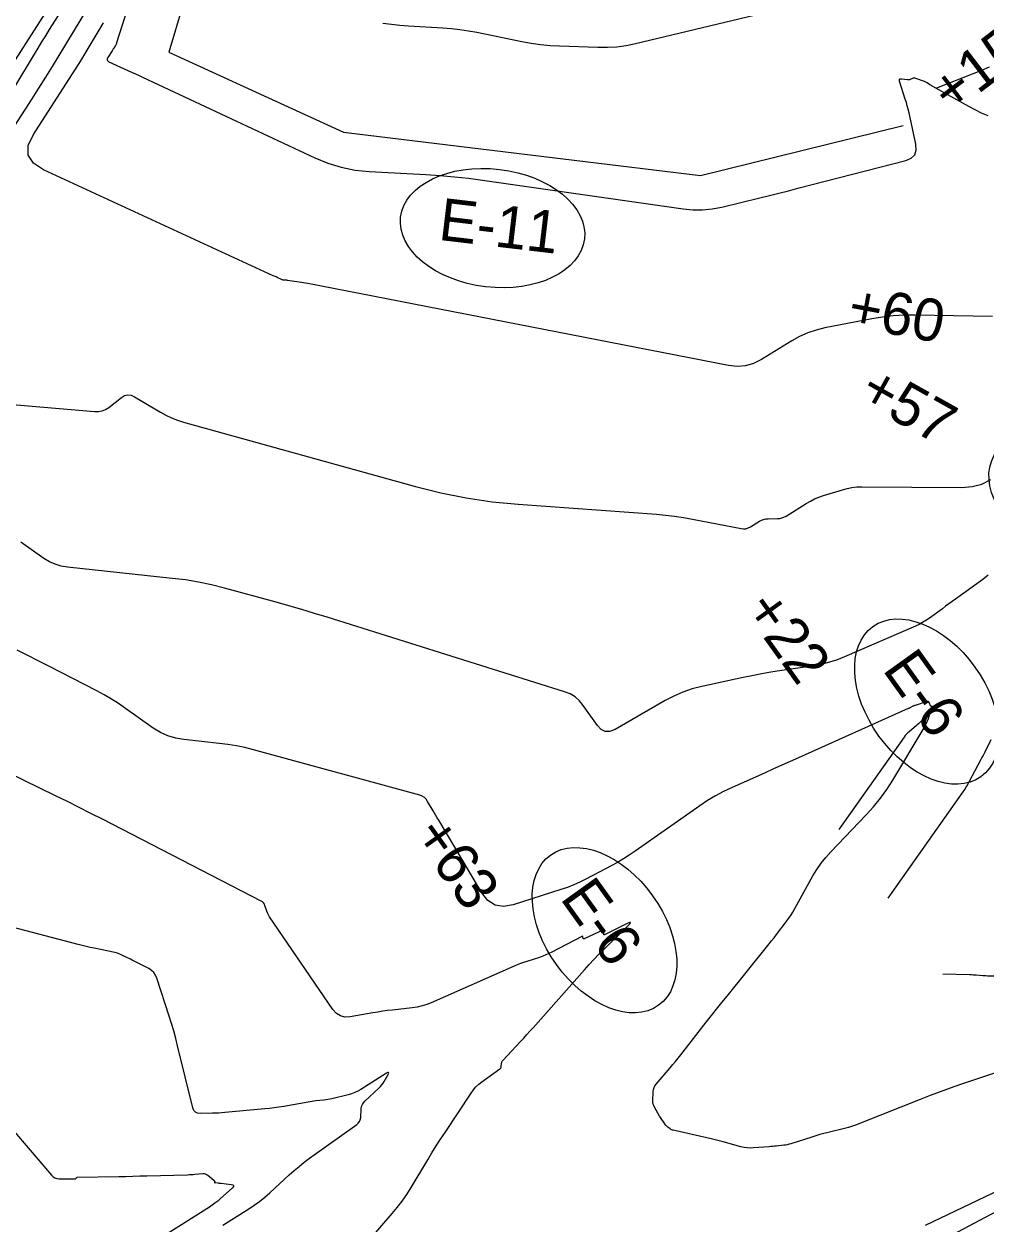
# Model space of a CAD drawing. Extents: x 1005228 to 1008882, y 1883389 to 1885754.
# Drawn here: x 1007862.3 to 1008004.6, y 1884352.9 to 1884530.4 of the extents above; entities that cross this region are included whole.
import ezdxf

# ---------------------------------------------------------------- set-up
doc = ezdxf.new("R2010")
doc.units = 0
for name, color, linetype in [('ATDIMS', 7, 'Continuous'), ('C-ANNO-NOTE', 7, 'Continuous'), ('R_Erosion', 7, 'Continuous'), ('S_BASELINE', 7, 'Continuous'), ('S_BRIDGE', 7, 'Continuous'), ('TSOBSTACLE', 7, 'Continuous')]:
    doc.layers.add(name, color=color, linetype=linetype)

msp = doc.modelspace()

# ---------------------------------------------------------------- linework, layer by layer
at = {"layer": 'ATDIMS'}
msp.add_lwpolyline([(1008005.05, 1884524.04), (1008003.94, 1884523.59), (1007997.3, 1884520.93)], dxfattribs=at)
at = {"layer": 'C-ANNO-NOTE'}
for points in [[(1007859.43, 1884522.69), (1007868.54, 1884536.99)], [(1007860.9, 1884521.17), (1007863.8, 1884525.98), (1007864.35, 1884526.89), (1007864.91, 1884527.8), (1007865.47, 1884528.71), (1007866.05, 1884529.61), (1007871.53, 1884538.23)], [(1007872.64, 1884534.47), (1007867.42, 1884525.79), (1007866.44, 1884524.17), (1007865.44, 1884522.56), (1007864.43, 1884520.96), (1007863.41, 1884519.36), (1007854.75, 1884505.98)], [(1007970.3, 1884531.71), (1007952.76, 1884527.51), (1007951.38, 1884527.23), (1007949.99, 1884527.04), (1007948.59, 1884526.95), (1007947.18, 1884526.96), (1007941.52, 1884527.16), (1007940.1, 1884527.24), (1007938.7, 1884527.37), (1007937.3, 1884527.57), (1007935.91, 1884527.82), (1007929.27, 1884529.17), (1007928.02, 1884529.4), (1007926.76, 1884529.58), (1007925.5, 1884529.73), (1007924.24, 1884529.83), (1007919.16, 1884530.14), (1007917.89, 1884530.23), (1007916.63, 1884530.36), (1007915.37, 1884530.52)], [(1008005.55, 1884487.18), (1007994.11, 1884487.37), (1007992.49, 1884487.36), (1007990.88, 1884487.26), (1007989.28, 1884487.08), (1007987.69, 1884486.81), (1007980.75, 1884485.46), (1007979.47, 1884485.16), (1007978.23, 1884484.74), (1007977.03, 1884484.21), (1007975.88, 1884483.57), (1007971.37, 1884480.78), (1007970.22, 1884480.2), (1007969.02, 1884479.86), (1007967.78, 1884479.76), (1007966.5, 1884479.9), (1007904.24, 1884492.05), (1007903.93, 1884492.11), (1007903.62, 1884492.16), (1007903.3, 1884492.21), (1007902.99, 1884492.26), (1007901.26, 1884492.51), (1007901.19, 1884492.52), (1007901.11, 1884492.53), (1007901.04, 1884492.53), (1007900.96, 1884492.54), (1007900.66, 1884492.55), (1007900.59, 1884492.56), (1007900.51, 1884492.58), (1007900.44, 1884492.6), (1007900.37, 1884492.63), (1007899.7, 1884492.94), (1007899.56, 1884493.01), (1007899.43, 1884493.07), (1007899.29, 1884493.13), (1007899.15, 1884493.19), (1007865.17, 1884508.86), (1007863.66, 1884509.84), (1007862.9, 1884511.04), (1007862.9, 1884512.46), (1007863.65, 1884514.1), (1007869.36, 1884522.92), (1007869.9, 1884523.77), (1007870.43, 1884524.61), (1007870.96, 1884525.47), (1007871.48, 1884526.33), (1007873.55, 1884529.77), (1007874.04, 1884530.64)], [(1007850.74, 1884474.99), (1007872.7, 1884473.08), (1007873.27, 1884473.08), (1007873.81, 1884473.19), (1007874.32, 1884473.4), (1007874.81, 1884473.71), (1007876.67, 1884475.17), (1007877.14, 1884475.45), (1007877.62, 1884475.56), (1007878.11, 1884475.51), (1007878.61, 1884475.29), (1007882.44, 1884473), (1007883.26, 1884472.54), (1007884.1, 1884472.14), (1007884.97, 1884471.81), (1007885.86, 1884471.53), (1007920.19, 1884462.01), (1007923.93, 1884461.07), (1007927.71, 1884460.32), (1007931.52, 1884459.75), (1007935.37, 1884459.38), (1007955.84, 1884457.89), (1007957.18, 1884457.77), (1007958.52, 1884457.61), (1007959.85, 1884457.41), (1007961.17, 1884457.18), (1007968.36, 1884455.77), (1007968.72, 1884455.73), (1007969.08, 1884455.76), (1007969.42, 1884455.86), (1007969.74, 1884456.03), (1007971.08, 1884456.85), (1007971.38, 1884457.01), (1007971.7, 1884457.13), (1007972.02, 1884457.2), (1007972.36, 1884457.23), (1007973.74, 1884457.25), (1007974.08, 1884457.28), (1007974.4, 1884457.36), (1007974.71, 1884457.47), (1007975.01, 1884457.63), (1007978.01, 1884459.5), (1007978.62, 1884459.85), (1007979.24, 1884460.16), (1007979.89, 1884460.43), (1007980.55, 1884460.66), (1007983.37, 1884461.53), (1007984.06, 1884461.72), (1007984.77, 1884461.85), (1007985.48, 1884461.93), (1007986.21, 1884461.95), (1008001.05, 1884461.85), (1008002.57, 1884461.98), (1008003.99, 1884462.37), (1008005.3, 1884463.04)], [(1008004.93, 1884448.87), (1008004.11, 1884448.25), (1008000.09, 1884445.33), (1007999.6, 1884444.97), (1007999.12, 1884444.62), (1007998.63, 1884444.27), (1007998.15, 1884443.92), (1007996.22, 1884442.52), (1007995.72, 1884442.18), (1007995.22, 1884441.87), (1007994.69, 1884441.59), (1007994.15, 1884441.34), (1007983.66, 1884436.79), (1007982.48, 1884436.32), (1007981.27, 1884435.93), (1007980.04, 1884435.62), (1007978.78, 1884435.4), (1007973.72, 1884434.65), (1007972.45, 1884434.45), (1007971.19, 1884434.23), (1007969.94, 1884433.99), (1007968.68, 1884433.73), (1007962.55, 1884432.4), (1007961.13, 1884432.04), (1007959.75, 1884431.57), (1007958.41, 1884430.99), (1007957.12, 1884430.31), (1007949.71, 1884426.04), (1007948.96, 1884425.73), (1007948.27, 1884425.73), (1007947.65, 1884426.02), (1007947.1, 1884426.62), (1007945.02, 1884429.6), (1007944.46, 1884430.29), (1007943.81, 1884430.85), (1007943.07, 1884431.3), (1007942.25, 1884431.63), (1007907.14, 1884442.64), (1007905.25, 1884443.22), (1007903.36, 1884443.79), (1007901.46, 1884444.34), (1007899.56, 1884444.87), (1007891.93, 1884446.95), (1007890.02, 1884447.44), (1007888.09, 1884447.84), (1007886.14, 1884448.17), (1007884.19, 1884448.41), (1007868.69, 1884450.06), (1007867.76, 1884450.22), (1007866.87, 1884450.49), (1007866.03, 1884450.87), (1007865.22, 1884451.37), (1007861.82, 1884453.78)], [(1008008.83, 1884376.17), (1008000.81, 1884373.49), (1007999.31, 1884372.97), (1007997.82, 1884372.44), (1007996.33, 1884371.88), (1007994.86, 1884371.3), (1007986.04, 1884367.77), (1007985.46, 1884367.55), (1007984.87, 1884367.34), (1007984.27, 1884367.16), (1007983.66, 1884367), (1007981.23, 1884366.41), (1007980.62, 1884366.26), (1007980.02, 1884366.09), (1007979.42, 1884365.92), (1007978.82, 1884365.73), (1007975.72, 1884364.73), (1007975.46, 1884364.65), (1007975.2, 1884364.59), (1007974.94, 1884364.54), (1007974.67, 1884364.51), (1007973.59, 1884364.39), (1007973.32, 1884364.36), (1007973.05, 1884364.34), (1007972.78, 1884364.31), (1007972.51, 1884364.29), (1007970.21, 1884364.11), (1007969.74, 1884364.09), (1007969.27, 1884364.12), (1007968.81, 1884364.18), (1007968.34, 1884364.29), (1007965.7, 1884365.02), (1007965.11, 1884365.18), (1007964.51, 1884365.33), (1007963.92, 1884365.48), (1007963.32, 1884365.61), (1007958.31, 1884366.72), (1007958.2, 1884366.76), (1007958.09, 1884366.8), (1007957.99, 1884366.85), (1007957.89, 1884366.92), (1007957.51, 1884367.21), (1007957.42, 1884367.28), (1007957.33, 1884367.37), (1007957.25, 1884367.45), (1007957.18, 1884367.55), (1007956.32, 1884368.77), (1007956.32, 1884368.77), (1007956.32, 1884368.78), (1007956.32, 1884368.78), (1007956.32, 1884368.78), (1007956.31, 1884368.8), (1007956.31, 1884368.8), (1007956.31, 1884368.8), (1007956.31, 1884368.81), (1007956.31, 1884368.81), (1007955.55, 1884370.14), (1007955.44, 1884370.37), (1007955.36, 1884370.61), (1007955.32, 1884370.85), (1007955.31, 1884371.1), (1007955.37, 1884372.46), (1007955.41, 1884372.76), (1007955.49, 1884373.05), (1007955.62, 1884373.31), (1007955.8, 1884373.56), (1007957.85, 1884375.96), (1007958.25, 1884376.44), (1007958.65, 1884376.92), (1007959.05, 1884377.41), (1007959.44, 1884377.91), (1007963.21, 1884382.74), (1007963.97, 1884383.7), (1007964.74, 1884384.67), (1007965.51, 1884385.63), (1007966.28, 1884386.59), (1007972.14, 1884393.85), (1007972.51, 1884394.31), (1007972.88, 1884394.77), (1007973.24, 1884395.23), (1007973.6, 1884395.7), (1007975.02, 1884397.57), (1007975.37, 1884398.05), (1007975.7, 1884398.53), (1007976.01, 1884399.03), (1007976.31, 1884399.54), (1007979, 1884404.37), (1007979.57, 1884405.33), (1007980.2, 1884406.24), (1007980.88, 1884407.11), (1007981.63, 1884407.94), (1007986.88, 1884413.41), (1007987.97, 1884414.61), (1007988.98, 1884415.86), (1007989.92, 1884417.17), (1007990.8, 1884418.53), (1007995.45, 1884426.28), (1007995.62, 1884426.58), (1007995.77, 1884426.89), (1007995.91, 1884427.2), (1007996.02, 1884427.53), (1007996.64, 1884429.45), (1007996.64, 1884429.47), (1007996.64, 1884429.48), (1007996.62, 1884429.49), (1007996.61, 1884429.48), (1007996.51, 1884429.43), (1007996.49, 1884429.42), (1007996.47, 1884429.42), (1007996.45, 1884429.43), (1007996.44, 1884429.45), (1007996.18, 1884430.03), (1007996.12, 1884430.11), (1007996.05, 1884430.17), (1007995.96, 1884430.18), (1007995.86, 1884430.17), (1007994.11, 1884429.61), (1007994.02, 1884429.58), (1007993.93, 1884429.54), (1007993.85, 1884429.51), (1007993.76, 1884429.47), (1007993.43, 1884429.3), (1007993.35, 1884429.25), (1007993.26, 1884429.21), (1007993.18, 1884429.17), (1007993.09, 1884429.13), (1007976.86, 1884421.86), (1007975.62, 1884421.3), (1007974.38, 1884420.75), (1007973.15, 1884420.2), (1007971.91, 1884419.64), (1007966.97, 1884417.43), (1007965.75, 1884416.85), (1007964.56, 1884416.21), (1007963.4, 1884415.51), (1007962.28, 1884414.76), (1007952.67, 1884408.02), (1007951.82, 1884407.44), (1007950.95, 1884406.89), (1007950.06, 1884406.36), (1007949.16, 1884405.87), (1007945.5, 1884403.94), (1007944.58, 1884403.48), (1007943.64, 1884403.06), (1007942.68, 1884402.68), (1007941.71, 1884402.35), (1007934.63, 1884400.1), (1007933.22, 1884399.85), (1007931.97, 1884400.06), (1007930.9, 1884400.73), (1007930.01, 1884401.86), (1007923.63, 1884412.62), (1007923.42, 1884412.96), (1007923.21, 1884413.31), (1007923.01, 1884413.66), (1007922.81, 1884414), (1007921.99, 1884415.4), (1007921.77, 1884415.72), (1007921.5, 1884415.97), (1007921.18, 1884416.17), (1007920.81, 1884416.31), (1007896.21, 1884423.04), (1007894.96, 1884423.36), (1007893.7, 1884423.62), (1007892.43, 1884423.83), (1007891.15, 1884423.99), (1007885.93, 1884424.55), (1007884.71, 1884424.75), (1007883.55, 1884425.11), (1007882.44, 1884425.61), (1007881.39, 1884426.26), (1007877.3, 1884429.16), (1007876.27, 1884429.87), (1007875.21, 1884430.54), (1007874.13, 1884431.17), (1007873.03, 1884431.76), (1007865.94, 1884435.42), (1007864.38, 1884436.21), (1007862.82, 1884437), (1007861.26, 1884437.78)], [(1007891.7, 1884352.67), (1007895.53, 1884355.08), (1007896.34, 1884355.62), (1007897.13, 1884356.19), (1007897.89, 1884356.81), (1007898.62, 1884357.45), (1007901.5, 1884360.11), (1007902.23, 1884360.76), (1007902.97, 1884361.39), (1007903.74, 1884361.99), (1007904.53, 1884362.58), (1007911.5, 1884367.56), (1007911.73, 1884367.77), (1007911.91, 1884368.01), (1007912.02, 1884368.29), (1007912.08, 1884368.6), (1007912.17, 1884369.91), (1007912.22, 1884370.23), (1007912.33, 1884370.52), (1007912.49, 1884370.78), (1007912.7, 1884371.02), (1007914.82, 1884373.01), (1007915.02, 1884373.22), (1007915.21, 1884373.45), (1007915.39, 1884373.68), (1007915.54, 1884373.93), (1007916.13, 1884374.96), (1007916.23, 1884375.17), (1007916.22, 1884375.27), (1007916.12, 1884375.27), (1007915.92, 1884375.16), (1007912.1, 1884372.77), (1007911.66, 1884372.51), (1007911.2, 1884372.3), (1007910.72, 1884372.12), (1007910.23, 1884371.98), (1007907.79, 1884371.4), (1007907.5, 1884371.33), (1007907.21, 1884371.28), (1007906.92, 1884371.23), (1007906.63, 1884371.19), (1007905.46, 1884371.06), (1007905.17, 1884371.03), (1007904.88, 1884370.99), (1007904.59, 1884370.94), (1007904.3, 1884370.9), (1007900.69, 1884370.27), (1007899.99, 1884370.15), (1007899.29, 1884370.05), (1007898.59, 1884369.97), (1007897.88, 1884369.89), (1007891.98, 1884369.35), (1007891.53, 1884369.31), (1007891.08, 1884369.28), (1007890.62, 1884369.26), (1007890.17, 1884369.25), (1007888.36, 1884369.2), (1007887.95, 1884369.24), (1007887.62, 1884369.4), (1007887.39, 1884369.67), (1007887.23, 1884370.05), (1007885, 1884379.21), (1007884.71, 1884380.32), (1007884.41, 1884381.43), (1007884.09, 1884382.53), (1007883.74, 1884383.63), (1007881.93, 1884389.22), (1007881.74, 1884389.67), (1007881.47, 1884390.06), (1007881.13, 1884390.38), (1007880.72, 1884390.65), (1007878.48, 1884391.8), (1007878.25, 1884391.92), (1007878.03, 1884392.03), (1007877.8, 1884392.14), (1007877.57, 1884392.26), (1007876.65, 1884392.7), (1007876.42, 1884392.81), (1007876.19, 1884392.9), (1007875.94, 1884392.97), (1007875.7, 1884393.03), (1007872.63, 1884393.66), (1007872.03, 1884393.79), (1007871.44, 1884393.93), (1007870.85, 1884394.07), (1007870.26, 1884394.22), (1007842.99, 1884401.39)], [(1007857.38, 1884370.56), (1007866.31, 1884360.1), (1007866.56, 1884359.86), (1007866.83, 1884359.7), (1007867.14, 1884359.6), (1007867.47, 1884359.56), (1007869.5, 1884359.56), (1007869.54, 1884359.56), (1007869.58, 1884359.56), (1007869.62, 1884359.56), (1007869.66, 1884359.56), (1007869.85, 1884359.56), (1007869.88, 1884359.56), (1007869.91, 1884359.57), (1007869.93, 1884359.58), (1007869.95, 1884359.61), (1007870.03, 1884359.71), (1007870.05, 1884359.74), (1007870.08, 1884359.75), (1007870.1, 1884359.76), (1007870.13, 1884359.77), (1007876.29, 1884359.89), (1007877.32, 1884359.91), (1007878.36, 1884359.94), (1007879.4, 1884359.96), (1007880.43, 1884359.99), (1007886.48, 1884360.15), (1007886.75, 1884360.16), (1007887.02, 1884360.17), (1007887.28, 1884360.19), (1007887.55, 1884360.21), (1007888.73, 1884360.32), (1007888.93, 1884360.32), (1007889.11, 1884360.28), (1007889.29, 1884360.2), (1007889.45, 1884360.09), (1007890.34, 1884359.34), (1007890.36, 1884359.31), (1007890.38, 1884359.29), (1007890.4, 1884359.27), (1007890.42, 1884359.24), (1007890.5, 1884359.11), (1007890.51, 1884359.09), (1007890.51, 1884359.08), (1007890.5, 1884359.07), (1007890.49, 1884359.06), (1007890.4, 1884359.02), (1007890.39, 1884359.01), (1007890.38, 1884359.01), (1007890.39, 1884359), (1007890.41, 1884359), (1007891, 1884358.93), (1007891.1, 1884358.92), (1007891.21, 1884358.91), (1007891.31, 1884358.89), (1007891.42, 1884358.88), (1007892.94, 1884358.7), (1007893.17, 1884358.64), (1007893.27, 1884358.54), (1007893.24, 1884358.41), (1007893.09, 1884358.23), (1007891.29, 1884356.57), (1007890.92, 1884356.24), (1007890.52, 1884355.92), (1007890.12, 1884355.62), (1007889.7, 1884355.35), (1007878.37, 1884348.2)]]:
    msp.add_lwpolyline(points, dxfattribs=at)
at = {"layer": 'R_Erosion'}
for points in [[(1007887.92, 1884540.52), (1007883.68, 1884526.3), (1007909.55, 1884514.42), (1007962.35, 1884508.01), (1007992.33, 1884515.45)], [(1007957.16, 1884335.93), (1007964.25, 1884332.53), (1008055.52, 1884380.91), (1008089.85, 1884389.28)]]:
    msp.add_lwpolyline(points, dxfattribs=at)
for centre, major_axis in [((1007931.59, 1884500.24), (13.6, -1.61)), ((1008017.73, 1884459.85), (11.96, -6.68)), ((1007995.86, 1884430.17), (7.99, -11.12)), ((1007948.16, 1884396.34), (7.99, -11.12))]:
    msp.add_ellipse(centre, major_axis=major_axis, ratio=0.638788, dxfattribs=at)
at = {"layer": 'S_BRIDGE'}
for points in [[(1007880.61, 1884542.2), (1007875.97, 1884527.67), (1007875.93, 1884527.57), (1007875.89, 1884527.46), (1007875.84, 1884527.36), (1007875.78, 1884527.26), (1007875.54, 1884526.87), (1007875.48, 1884526.77), (1007875.42, 1884526.67), (1007875.36, 1884526.57), (1007875.3, 1884526.48), (1007874.65, 1884525.47), (1007874.56, 1884525.28), (1007874.56, 1884525.12), (1007874.65, 1884524.98), (1007874.82, 1884524.87), (1007877.65, 1884523.57), (1007878.19, 1884523.32), (1007878.74, 1884523.06), (1007879.28, 1884522.81), (1007879.82, 1884522.56), (1007905.29, 1884510.63), (1007907.23, 1884509.84), (1007909.21, 1884509.24), (1007911.24, 1884508.83), (1007913.32, 1884508.62), (1007921.74, 1884508.16), (1007923.84, 1884508.02), (1007925.94, 1884507.84), (1007928.03, 1884507.61), (1007930.12, 1884507.33), (1007959.8, 1884503.08), (1007961.23, 1884502.94), (1007962.66, 1884502.94), (1007964.08, 1884503.08), (1007965.5, 1884503.35), (1007971.15, 1884504.73), (1007972.56, 1884505.07), (1007973.97, 1884505.42), (1007975.38, 1884505.78), (1007976.78, 1884506.14), (1007992.74, 1884510.27), (1007993.54, 1884510.6), (1007994.05, 1884511.11), (1007994.27, 1884511.79), (1007994.21, 1884512.65), (1007993.21, 1884517.3), (1007993.09, 1884517.82), (1007992.96, 1884518.33), (1007992.82, 1884518.84), (1007992.66, 1884519.34), (1007991.82, 1884522.01), (1007991.79, 1884522.16), (1007991.82, 1884522.27), (1007991.92, 1884522.32), (1007992.08, 1884522.32), (1007993.01, 1884522.21), (1007993.12, 1884522.21), (1007993.22, 1884522.22), (1007993.31, 1884522.24), (1007993.41, 1884522.27), (1007993.79, 1884522.44), (1007993.89, 1884522.47), (1007993.98, 1884522.49), (1007994.08, 1884522.48), (1007994.18, 1884522.45), (1007995.45, 1884522), (1007995.56, 1884521.95), (1007995.67, 1884521.9), (1007995.77, 1884521.84), (1007995.88, 1884521.78), (1007996.28, 1884521.51), (1007996.38, 1884521.45), (1007996.48, 1884521.38), (1007996.59, 1884521.32), (1007996.69, 1884521.26), (1008002.02, 1884518.29), (1008002.95, 1884517.79), (1008003.89, 1884517.32), (1008004.86, 1884516.89)], [(1007911.86, 1884348.75), (1007916.73, 1884354.39), (1007917.49, 1884355.31), (1007918.21, 1884356.26), (1007918.89, 1884357.24), (1007919.53, 1884358.26), (1007922, 1884362.36), (1007922.63, 1884363.39), (1007923.26, 1884364.4), (1007923.9, 1884365.41), (1007924.56, 1884366.42), (1007928.41, 1884372.24), (1007928.75, 1884372.71), (1007929.13, 1884373.15), (1007929.55, 1884373.54), (1007930.01, 1884373.9), (1007932.69, 1884375.82), (1007932.77, 1884375.89), (1007932.83, 1884375.98), (1007932.87, 1884376.07), (1007932.89, 1884376.18), (1007932.92, 1884376.64), (1007932.94, 1884376.75), (1007932.98, 1884376.85), (1007933.03, 1884376.94), (1007933.1, 1884377.03), (1007935.74, 1884379.87), (1007936.21, 1884380.37), (1007936.67, 1884380.88), (1007937.13, 1884381.39), (1007937.59, 1884381.9), (1007945.2, 1884390.49), (1007945.89, 1884391.26), (1007946.6, 1884392.02), (1007947.33, 1884392.77), (1007948.06, 1884393.5), (1007951.62, 1884396.98), (1007951.95, 1884397.32), (1007952.02, 1884397.49), (1007951.84, 1884397.48), (1007951.4, 1884397.28), (1007948.24, 1884395.68), (1007948.16, 1884395.65), (1007948.1, 1884395.66), (1007948.07, 1884395.71), (1007948.08, 1884395.8), (1007948.16, 1884396.24), (1007948.16, 1884396.34), (1007948.13, 1884396.39), (1007948.08, 1884396.4), (1007947.99, 1884396.37), (1007945.14, 1884395.05), (1007945.09, 1884395.04), (1007945.05, 1884395.04), (1007945.02, 1884395.07), (1007945, 1884395.12), (1007944.93, 1884395.36), (1007944.91, 1884395.41), (1007944.88, 1884395.43), (1007944.84, 1884395.44), (1007944.79, 1884395.42), (1007940.37, 1884393.09), (1007939.93, 1884392.87), (1007939.47, 1884392.67), (1007939.01, 1884392.48), (1007938.54, 1884392.32), (1007936.64, 1884391.72), (1007936.17, 1884391.56), (1007935.71, 1884391.39), (1007935.24, 1884391.21), (1007934.78, 1884391.02), (1007922.53, 1884385.61), (1007921.85, 1884385.34), (1007921.16, 1884385.12), (1007920.45, 1884384.96), (1007919.72, 1884384.85), (1007916.8, 1884384.52), (1007916.07, 1884384.43), (1007915.34, 1884384.33), (1007914.61, 1884384.22), (1007913.89, 1884384.1), (1007910.5, 1884383.51), (1007909.74, 1884383.48), (1007909.07, 1884383.64), (1007908.48, 1884384.01), (1007907.97, 1884384.58), (1007898.6, 1884398.31), (1007898.48, 1884398.51), (1007898.37, 1884398.71), (1007898.28, 1884398.91), (1007898.2, 1884399.13), (1007897.92, 1884400), (1007897.83, 1884400.2), (1007897.71, 1884400.38), (1007897.56, 1884400.53), (1007897.37, 1884400.64), (1007873.88, 1884412.75), (1007872.16, 1884413.63), (1007870.42, 1884414.51), (1007868.68, 1884415.37), (1007866.94, 1884416.23), (1007859.95, 1884419.63)], [(1008006.67, 1884357.9), (1007995.6, 1884352.61)]]:
    msp.add_lwpolyline(points, dxfattribs=at)
at = {"layer": 'TSOBSTACLE'}
for points in [[(1007996.14, 1884428.58), (1007996.54, 1884428.79), (1007996.59, 1884428.81), (1007996.61, 1884428.82), (1007996.6, 1884428.8), (1007996.56, 1884428.75), (1007996.05, 1884428.23), (1007995.94, 1884428.12), (1007995.84, 1884428.02), (1007995.73, 1884427.92), (1007995.62, 1884427.82), (1007994.9, 1884427.16), (1007994.74, 1884427.02), (1007994.59, 1884426.87), (1007994.43, 1884426.73), (1007994.26, 1884426.6), (1007993.26, 1884425.74), (1007993.05, 1884425.55), (1007992.85, 1884425.34), (1007992.66, 1884425.13), (1007992.49, 1884424.89), (1007982.84, 1884411.23)], [(1007990.13, 1884401.08), (1008001.23, 1884416.8), (1008001.38, 1884417.01), (1008001.51, 1884417.22), (1008001.64, 1884417.44), (1008001.77, 1884417.66), (1008003.84, 1884421.53), (1008004, 1884421.83), (1008004.16, 1884422.12), (1008004.31, 1884422.42), (1008004.46, 1884422.72), (1008005.38, 1884424.55)], [(1008009.8, 1884389.54), (1008005.05, 1884389.54), (1008004.81, 1884389.55), (1008004.58, 1884389.56), (1008004.34, 1884389.57), (1008004.11, 1884389.59), (1008003.17, 1884389.67), (1008002.93, 1884389.69), (1008002.7, 1884389.7), (1008002.46, 1884389.72), (1008002.23, 1884389.72), (1007998.22, 1884389.82)]]:
    msp.add_lwpolyline(points, dxfattribs=at)

# ---------------------------------------------------------------- texts
at = {"layer": 'R_Erosion'}
for s, rotation, p in [('E-11', 353.2487, (1007923.45, 1884498.52)), ('E-6', 305.6982, (1007989.17, 1884434.91)), ('E-6', 305.6982, (1007941.47, 1884401.08))]:
    msp.add_text(s, height=6.25, rotation=rotation, dxfattribs=at).set_placement(p)
at = {"layer": 'S_BASELINE'}
for s, rotation, p in [('+15', 37.388, (1007999.51, 1884517.01)), ('+60', 349.3276, (1007983.87, 1884485.83)), ('+57', 330.815, (1007985.46, 1884474.82)), ('+22', 305.6982, (1007968.61, 1884443.8)), ('+63', 305.6982, (1007919.63, 1884410.34))]:
    msp.add_text(s, height=6.25, rotation=rotation, dxfattribs=at).set_placement(p)

doc.saveas('drawing.dxf')
